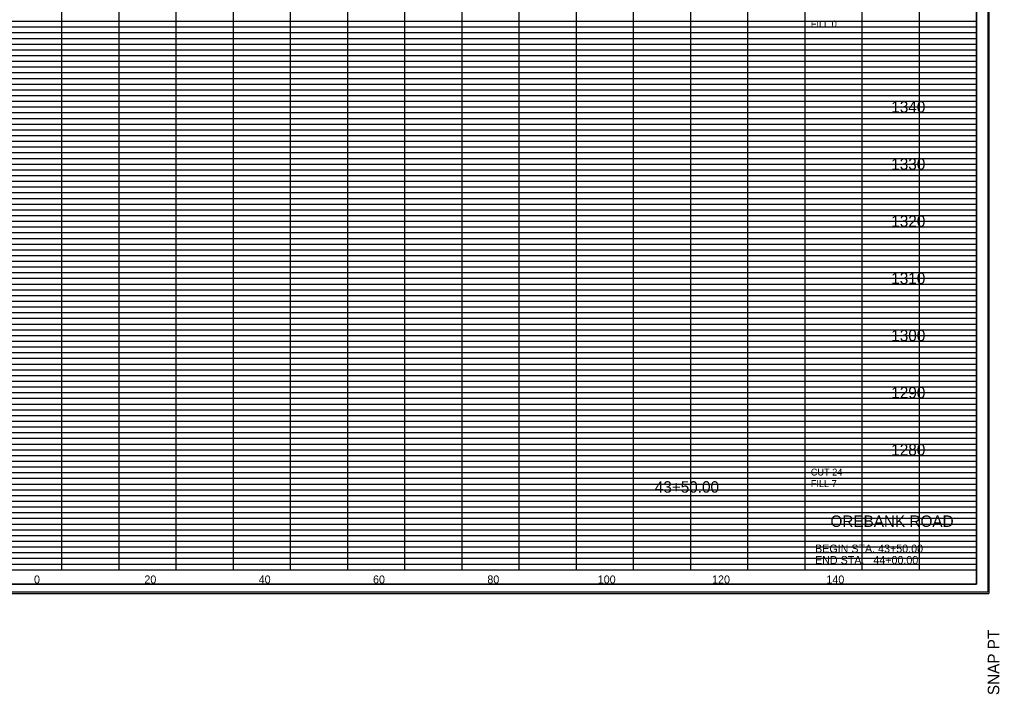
# Model space of a CAD drawing. Extents: x 980 to 1324, y 978 to 2847.
# Drawn here: x 1152.6 to 1324, y 1248.2 to 1366.3 of the extents above; entities that cross this region are included whole.
import ezdxf

# ---------------------------------------------------------------- set-up
doc = ezdxf.new("R2010")
doc.units = 0
for name, color, linetype in [('DESIGN - SHEET - Corner Text', 7, 'Continuous'), ('DESIGN - SHEET - Light Grid', 7, 'Continuous'), ('DESIGN - SHEET - Linework', 7, 'Continuous'), ('DESIGN - SHEET - Plot Shape', 7, 'Continuous'), ('DESIGN - TYPICAL - Text', 7, 'Continuous')]:
    doc.layers.add(name, color=color, linetype=linetype)

# ---------------------------------------------------------------- blocks, each defined once
blk = doc.blocks.new('XSTSHT')
at = {"layer": 'DESIGN - SHEET - Light Grid'}
for p, q in [((8, 9.6), (16, 9.6)), ((16, 9.6), (24, 9.6)), ((24, 9.6), (32, 9.6)), ((8, 9.5), (16, 9.5)), ((16, 9.5), (24, 9.5)), ((24, 9.5), (32, 9.5)), ((8, 9.4), (16, 9.4)), ((8, 9.3), (16, 9.3)), ((16, 9.4), (24, 9.4)), ((16, 9.3), (24, 9.3)), ((24, 9.4), (32, 9.4)), ((24, 9.3), (32, 9.3)), ((8, 9.2), (16, 9.2)), ((8, 9.1), (16, 9.1)), ((16, 9.2), (24, 9.2)), ((16, 9.1), (24, 9.1)), ((24, 9.2), (32, 9.2)), ((24, 9.1), (32, 9.1)), ((8, 8.9), (16, 8.9)), ((8, 8.8), (16, 8.8)), ((16, 8.9), (24, 8.9)), ((16, 8.8), (24, 8.8)), ((24, 8.9), (32, 8.9)), ((24, 8.8), (32, 8.8)), ((8, 8.7), (16, 8.7)), ((8, 8.6), (16, 8.6)), ((16, 8.7), (24, 8.7)), ((16, 8.6), (24, 8.6)), ((24, 8.7), (32, 8.7)), ((24, 8.6), (32, 8.6)), ((8, 8.5), (16, 8.5)), ((8, 8.4), (16, 8.4)), ((16, 8.5), (24, 8.5)), ((16, 8.4), (24, 8.4)), ((24, 8.5), (32, 8.5)), ((24, 8.4), (32, 8.4)), ((8, 8.3), (16, 8.3)), ((16, 8.3), (24, 8.3)), ((24, 8.3), (32, 8.3)), ((8, 8.2), (16, 8.2)), ((8, 8.1), (16, 8.1)), ((16, 8.2), (24, 8.2)), ((16, 8.1), (24, 8.1)), ((24, 8.2), (32, 8.2)), ((24, 8.1), (32, 8.1)), ((8, 7.9), (16, 7.9)), ((16, 7.9), (24, 7.9)), ((24, 7.9), (32, 7.9)), ((8, 7.8), (16, 7.8)), ((16, 7.8), (24, 7.8)), ((24, 7.8), (32, 7.8)), ((8, 7.7), (16, 7.7)), ((8, 7.6), (16, 7.6)), ((16, 7.7), (24, 7.7)), ((16, 7.6), (24, 7.6)), ((24, 7.7), (32, 7.7)), ((24, 7.6), (32, 7.6)), ((8, 7.5), (16, 7.5)), ((8, 7.4), (16, 7.4)), ((16, 7.5), (24, 7.5)), ((16, 7.4), (24, 7.4)), ((24, 7.5), (32, 7.5)), ((24, 7.4), (32, 7.4)), ((8, 7.3), (16, 7.3)), ((8, 7.2), (16, 7.2)), ((16, 7.3), (24, 7.3)), ((16, 7.2), (24, 7.2)), ((24, 7.3), (32, 7.3)), ((24, 7.2), (32, 7.2)), ((8, 7.1), (16, 7.1)), ((16, 7.1), (24, 7.1)), ((24, 7.1), (32, 7.1)), ((8, 6.9), (16, 6.9)), ((16, 6.9), (24, 6.9)), ((24, 6.9), (32, 6.9)), ((8, 6.8), (16, 6.8)), ((8, 6.7), (16, 6.7)), ((16, 6.8), (24, 6.8)), ((16, 6.7), (24, 6.7)), ((24, 6.8), (32, 6.8)), ((24, 6.7), (32, 6.7)), ((8, 6.6), (16, 6.6)), ((16, 6.6), (24, 6.6)), ((24, 6.6), (32, 6.6)), ((8, 6.5), (16, 6.5)), ((8, 6.4), (16, 6.4)), ((16, 6.5), (24, 6.5)), ((16, 6.4), (24, 6.4)), ((24, 6.5), (32, 6.5)), ((24, 6.4), (32, 6.4)), ((8, 6.3), (16, 6.3)), ((8, 6.2), (16, 6.2)), ((16, 6.3), (24, 6.3)), ((16, 6.2), (24, 6.2)), ((24, 6.3), (32, 6.3)), ((24, 6.2), (32, 6.2)), ((8, 6.1), (16, 6.1)), ((16, 6.1), (24, 6.1)), ((24, 6.1), (32, 6.1)), ((8, 5.9), (16, 5.9)), ((16, 5.9), (24, 5.9)), ((24, 5.9), (32, 5.9)), ((8, 5.8), (16, 5.8)), ((8, 5.7), (16, 5.7)), ((16, 5.8), (24, 5.8)), ((16, 5.7), (24, 5.7)), ((24, 5.8), (32, 5.8)), ((24, 5.7), (32, 5.7)), ((8, 5.6), (16, 5.6)), ((8, 5.5), (16, 5.5)), ((16, 5.6), (24, 5.6)), ((16, 5.5), (24, 5.5)), ((24, 5.6), (32, 5.6)), ((24, 5.5), (32, 5.5)), ((8, 5.4), (16, 5.4)), ((16, 5.4), (24, 5.4)), ((24, 5.4), (32, 5.4)), ((8, 5.3), (16, 5.3)), ((8, 5.2), (16, 5.2)), ((16, 5.3), (24, 5.3)), ((16, 5.2), (24, 5.2)), ((24, 5.3), (32, 5.3)), ((24, 5.2), (32, 5.2)), ((8, 5.1), (16, 5.1)), ((16, 5.1), (24, 5.1)), ((24, 5.1), (32, 5.1)), ((8, 4.9), (16, 4.9)), ((8, 4.8), (16, 4.8)), ((16, 4.9), (24, 4.9)), ((16, 4.8), (24, 4.8)), ((24, 4.9), (32, 4.9)), ((24, 4.8), (32, 4.8)), ((8, 4.7), (16, 4.7)), ((16, 4.7), (24, 4.7)), ((24, 4.7), (32, 4.7)), ((8, 4.6), (16, 4.6)), ((8, 4.5), (16, 4.5)), ((16, 4.6), (24, 4.6)), ((16, 4.5), (24, 4.5)), ((24, 4.6), (32, 4.6)), ((24, 4.5), (32, 4.5)), ((8, 4.4), (16, 4.4)), ((8, 4.3), (16, 4.3)), ((16, 4.4), (24, 4.4)), ((16, 4.3), (24, 4.3)), ((24, 4.4), (32, 4.4)), ((24, 4.3), (32, 4.3)), ((8, 4.2), (16, 4.2)), ((16, 4.2), (24, 4.2)), ((24, 4.2), (32, 4.2)), ((8, 4.1), (16, 4.1)), ((16, 4.1), (24, 4.1)), ((24, 4.1), (32, 4.1)), ((8, 3.9), (16, 3.9)), ((8, 3.8), (16, 3.8)), ((16, 3.9), (24, 3.9)), ((16, 3.8), (24, 3.8)), ((24, 3.9), (32, 3.9)), ((24, 3.8), (32, 3.8)), ((8, 3.7), (16, 3.7)), ((8, 3.6), (16, 3.6)), ((16, 3.7), (24, 3.7)), ((16, 3.6), (24, 3.6)), ((24, 3.7), (32, 3.7)), ((24, 3.6), (32, 3.6)), ((8, 3.5), (16, 3.5)), ((16, 3.5), (24, 3.5)), ((24, 3.5), (32, 3.5)), ((8, 3.4), (16, 3.4)), ((8, 3.3), (16, 3.3)), ((16, 3.4), (24, 3.4)), ((16, 3.3), (24, 3.3)), ((24, 3.4), (32, 3.4)), ((24, 3.3), (32, 3.3)), ((8, 3.2), (16, 3.2)), ((8, 3.1), (16, 3.1)), ((16, 3.2), (24, 3.2)), ((16, 3.1), (24, 3.1)), ((24, 3.2), (32, 3.2)), ((24, 3.1), (32, 3.1)), ((8, 2.9), (16, 2.9)), ((8, 2.8), (16, 2.8)), ((16, 2.9), (24, 2.9)), ((16, 2.8), (24, 2.8)), ((24, 2.9), (32, 2.9)), ((24, 2.8), (32, 2.8)), ((8, 2.7), (16, 2.7)), ((8, 2.6), (16, 2.6)), ((16, 2.7), (24, 2.7)), ((16, 2.6), (24, 2.6)), ((24, 2.7), (32, 2.7)), ((24, 2.6), (32, 2.6)), ((8, 2.5), (16, 2.5)), ((8, 2.4), (16, 2.4)), ((16, 2.5), (24, 2.5)), ((16, 2.4), (24, 2.4)), ((24, 2.5), (32, 2.5)), ((24, 2.4), (32, 2.4)), ((8, 2.3), (16, 2.3)), ((16, 2.3), (24, 2.3)), ((24, 2.3), (32, 2.3)), ((8, 2.2), (16, 2.2)), ((8, 2.1), (16, 2.1)), ((16, 2.2), (24, 2.2)), ((16, 2.1), (24, 2.1)), ((24, 2.2), (32, 2.2)), ((24, 2.1), (32, 2.1)), ((8, 1.9), (16, 1.9)), ((16, 1.9), (24, 1.9)), ((24, 1.9), (32, 1.9)), ((8, 1.8), (16, 1.8)), ((16, 1.8), (24, 1.8)), ((24, 1.8), (32, 1.8)), ((8, 1.7), (16, 1.7)), ((8, 1.6), (16, 1.6)), ((16, 1.7), (24, 1.7)), ((16, 1.6), (24, 1.6)), ((24, 1.7), (32, 1.7)), ((24, 1.6), (32, 1.6)), ((8, 1.5), (16, 1.5)), ((8, 1.4), (16, 1.4)), ((16, 1.5), (24, 1.5)), ((16, 1.4), (24, 1.4)), ((24, 1.5), (32, 1.5)), ((24, 1.4), (32, 1.4)), ((8, 1.3), (16, 1.3)), ((8, 1.2), (16, 1.2)), ((16, 1.3), (24, 1.3)), ((16, 1.2), (24, 1.2)), ((24, 1.3), (32, 1.3)), ((24, 1.2), (32, 1.2)), ((8, 1.1), (16, 1.1)), ((16, 1.1), (24, 1.1)), ((24, 1.1), (32, 1.1)), ((8, 0.9), (16, 0.9)), ((16, 0.9), (24, 0.9)), ((24, 0.9), (32, 0.9)), ((8, 0.8), (16, 0.8)), ((8, 0.7), (16, 0.7)), ((16, 0.8), (24, 0.8)), ((16, 0.7), (24, 0.7)), ((24, 0.8), (32, 0.8)), ((24, 0.7), (32, 0.7)), ((8, 0.6), (16, 0.6)), ((16, 0.6), (24, 0.6)), ((24, 0.6), (32, 0.6)), ((8, 0.5), (16, 0.5)), ((8, 0.4), (16, 0.4)), ((16, 0.5), (24, 0.5)), ((16, 0.4), (24, 0.4)), ((24, 0.5), (32, 0.5)), ((24, 0.4), (32, 0.4)), ((8, 0.3), (16, 0.3)), ((8, 0.2), (16, 0.2)), ((16, 0.3), (24, 0.3)), ((16, 0.2), (24, 0.2)), ((24, 0.3), (32, 0.3)), ((24, 0.2), (32, 0.2)), ((8, 0.1), (16, 0.1)), ((16, 0.1), (24, 0.1)), ((24, 0.1), (32, 0.1))]:
    blk.add_line(p, q, dxfattribs=at)
at = {"layer": 'DESIGN - SHEET - Linework'}
for p, q in [((32.217, 21.414), (32.217, -0.414)), ((16, 0), (16, 21)), ((17, 0), (17, 21)), ((18, 0), (18, 21)), ((19, 0), (19, 21)), ((20, 0), (20, 21)), ((21, 0), (21, 21)), ((22, 0), (22, 21)), ((23, 0), (23, 21)), ((24, 0), (24, 21)), ((25, 0), (25, 21)), ((26, 0), (26, 21)), ((27, 0), (27, 21)), ((28, 0), (28, 20)), ((29, 0), (29, 20)), ((30, 0), (30, 20)), ((31, 0), (31, 20)), ((0, 9), (32, 9)), ((0, 8), (32, 8)), ((0, 7), (32, 7)), ((0, 6), (32, 6)), ((0, 5), (32, 5)), ((0, 4), (32, 4)), ((0, 3), (32, 3)), ((0, 2), (32, 2)), ((0, 1), (32, 1)), ((-1.823, -0.414), (32.217, -0.414))]:
    blk.add_line(p, q, dxfattribs=at)
blk.add_lwpolyline([(0, 21), (0, 0), (32, 0), (32, 21), (0, 21)], dxfattribs=at)
at = {"layer": 'DESIGN - SHEET - Plot Shape'}
for points in [[(-1.803, 21.394), (32.197, 21.394), (32.197, -0.394), (-1.803, -0.394)], [(-0.85, 21), (32, 21), (32, -0.25), (-0.85, -0.25)]]:
    blk.add_lwpolyline(points, close=True, dxfattribs=at)
at = {"layer": 'DESIGN - SHEET - Corner Text'}
blk.add_text('SNAP PT  ', height=0.2, rotation=90, dxfattribs=at).set_placement((32.397, -2.194))

msp = doc.modelspace()

# ---------------------------------------------------------------- linework, layer by layer
at = {"layer": 'DESIGN - SHEET - Plot Shape'}
msp.add_lwpolyline([(991.5, 1267.5), (1320, 1267.5), (1320, 1480), (991.5, 1480)], close=True, dxfattribs=at)

# ---------------------------------------------------------------- block references
at = {"layer": 'DESIGN - SHEET - Plot Shape', "xscale": 10, "yscale": 10}
msp.add_blockref('XSTSHT', (1000, 1270), dxfattribs=at)

# ---------------------------------------------------------------- texts
at = {"layer": 'DESIGN - SHEET - Corner Text'}
for s, height, p in [('OREBANK ROAD', 2, (1294.44, 1277.5)), ('BEGIN STA. 43+50.00', 1.4, (1291.75, 1273)), ('END STA.   44+00.00', 1.4, (1291.75, 1271))]:
    msp.add_text(s, height=height, dxfattribs=at).set_placement(p)
at = {"layer": 'DESIGN - TYPICAL - Text'}
for s, height, p in [('FILL 0', 1.2, (1291, 1364.92)), ('     1340     ', 2, (1301.37, 1350)), ('     1330     ', 2, (1301.37, 1340)), ('     1320     ', 2, (1301.37, 1330)), ('     1310     ', 2, (1301.37, 1320)), ('     1300     ', 2, (1301.37, 1310)), ('     1290     ', 2, (1301.37, 1300)), ('     1280     ', 2, (1301.37, 1290)), ('CUT 24', 1.2, (1291, 1286.49)), ('FILL 7', 1.2, (1291, 1284.49)), ('     43+50.00     ', 2, (1260, 1283.49)), ('     0     ', 1.4, (1152.51, 1267.6)), ('     0     ', 1.4, (1152.51, 1267.6)), ('     20     ', 1.4, (1171.82, 1267.6)), ('     40     ', 1.4, (1191.82, 1267.6)), ('     60     ', 1.4, (1211.82, 1267.6)), ('     80     ', 1.4, (1231.82, 1267.6)), ('     100     ', 1.4, (1251.14, 1267.6)), ('     120     ', 1.4, (1271.14, 1267.6)), ('     140     ', 1.4, (1291.14, 1267.6))]:
    msp.add_text(s, height=height, dxfattribs=at).set_placement(p)

doc.saveas('drawing.dxf')
